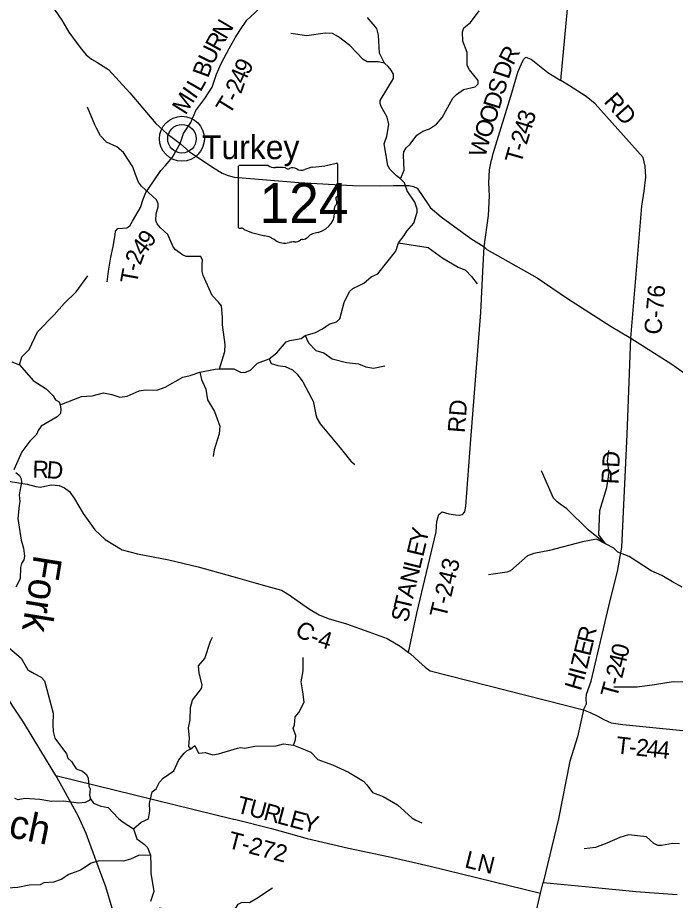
# Model space of a CAD drawing. Extents: x 1525783 to 1900577, y 218250 to 627376.
# Drawn here: x 1696377 to 1707878, y 391777 to 407202 of the extents above; entities that cross this region are included whole.
import ezdxf

# ---------------------------------------------------------------- set-up
doc = ezdxf.new("R2010")
doc.units = 0
for name, color, linetype in [('GM_X_County_Road', 7, 'Continuous'), ('GM_X_County_Road_Text', 7, 'Continuous'), ('GM_X_Minor_River', 7, 'Continuous'), ('GM_X_Minor_River_Text', 7, 'Continuous'), ('GM_X_State_Location', 7, 'Continuous'), ('GM_X_State_Route', 7, 'Continuous'), ('GM_X_State_Shield', 7, 'Continuous'), ('GM_X_Township_Road', 7, 'Continuous'), ('GM_X_Township_Road_Text', 7, 'Continuous'), ('GM_X_Township_ROW', 7, 'Continuous'), ('GM_X_Unincorporated', 7, 'Continuous'), ('GM_X_Unincorporated_Location', 7, 'Continuous'), ('GM_X_Unincorporated_Text', 7, 'Continuous')]:
    doc.layers.add(name, color=color, linetype=linetype)

msp = doc.modelspace()

# ---------------------------------------------------------------- linework, layer by layer
at = {"layer": 'GM_X_County_Road'}
for points in [[(1707101, 401600), (1707294, 403908), (1707330, 404169), (1707360, 404415), (1707349, 404606), (1707314, 404758), (1706872, 405256), (1706475, 405699), (1706320, 405822), (1706009, 406023), (1705874, 406102), (1706079, 408301)], [(1698028, 391638), (1697920, 392012), (1697790, 392354), (1697577, 392945), (1697433, 393255), (1697123, 393824), (1697042, 393959), (1696781, 394389), (1696480, 394888), (1696280, 395190), (1696157, 395389), (1696091, 395495), (1695978, 395695), (1695575, 396785), (1695426, 397233), (1695305, 397657), (1695289, 397853), (1695689, 399162)], [(1695956, 399142), (1696541, 399047), (1696696, 399008), (1696776, 398995), (1696850, 399017), (1696966, 399036), (1697104, 399025), (1697194, 398985), (1697285, 398922), (1697374, 398794), (1697524, 398538), (1697728, 398253), (1697905, 398080), (1698204, 397903), (1698471, 397831), (1699022, 397726), (1699536, 397603), (1700139, 397434), (1700545, 397320), (1700737, 397266), (1700988, 397195), (1701127, 397116), (1701464, 396875), (1701649, 396764), (1701808, 396701), (1702129, 396609), (1702516, 396469), (1702837, 396355), (1703068, 396220), (1703212, 396110), (1703247, 396083), (1703390, 395949), (1703505, 395854), (1703588, 395788), (1706273, 395107), (1706166, 394633), (1706035, 394208), (1705837, 393203), (1705564, 392091), (1706425, 392010), (1707187, 391934), (1707908, 391879)]]:
    msp.add_lwpolyline(points, dxfattribs=at)
at = {"layer": 'GM_X_Minor_River'}
for points in [[(1703073, 404385), (1703133, 404537), (1703124, 404799), (1703132, 404857), (1703171, 404927), (1703243, 404994), (1703355, 405147), (1703465, 405220), (1703580, 405259), (1703704, 405342), (1703803, 405459), (1703986, 405795), (1704049, 405861), (1704172, 405947), (1704380, 405991), (1704430, 406045), (1704431, 406103), (1704277, 406291), (1704236, 406367), (1704238, 406591), (1704162, 406790), (1704158, 406952), (1704178, 407026), (1704295, 407115), (1704447, 407322)], [(1697121, 400436), (1697496, 400583), (1697680, 400593), (1697879, 400645), (1698024, 400618), (1698162, 400572), (1698292, 400589), (1698502, 400679), (1698610, 400696), (1698810, 400694), (1698954, 400743), (1699264, 400922), (1699394, 400947), (1699562, 401007), (1699832, 401060), (1699908, 401066), (1700156, 401063), (1700275, 401006), (1700347, 400999), (1700451, 401040), (1700571, 401165), (1700773, 401241), (1700912, 401346), (1701072, 401537), (1701136, 401562), (1701336, 401598), (1701402, 401647), (1701587, 401702), (1701705, 401762), (1701824, 401845), (1701950, 401886), (1702012, 401942), (1702085, 402223), (1702177, 402416), (1702239, 402472), (1702362, 402529), (1702428, 402560), (1702557, 402673), (1702673, 402728), (1702991, 403123), (1703036, 403267), (1703138, 403394), (1703182, 403473), (1703307, 403610), (1703363, 403802), (1703362, 403858), (1703323, 403976), (1703191, 404176), (1703143, 404318), (1703073, 404385), (1703002, 404438), (1702883, 404553), (1702850, 404617), (1702784, 404996), (1702831, 405132), (1702867, 405338), (1702837, 405466), (1702734, 405647), (1702715, 405700), (1702718, 405754), (1702951, 406138), (1702948, 406216), (1702909, 406286), (1702857, 406347), (1702790, 406409), (1702706, 406580), (1702685, 406895), (1702656, 407011), (1702494, 407207)], [(1702790, 406409), (1702682, 406432), (1702487, 406428), (1702421, 406469), (1702184, 406713), (1701987, 406866), (1701880, 406923), (1701754, 406934), (1701432, 406887), (1701153, 406928)], [(1699908, 401066), (1700001, 401371), (1700004, 401493), (1699962, 401832), (1699961, 401970), (1699939, 402164), (1699892, 402233), (1699781, 402348), (1699623, 402698), (1699602, 402766), (1699603, 402886), (1699612, 402962), (1699578, 403030), (1699323, 403029), (1699257, 403057), (1699136, 403145), (1699095, 403199), (1699005, 403412), (1698876, 403531), (1698817, 403600), (1698791, 403658), (1698801, 403774), (1698836, 403896), (1698836, 403946), (1698807, 404017), (1698540, 404257), (1698490, 404326), (1698440, 404460), (1698391, 404595), (1698230, 404845), (1698111, 404942), (1697928, 405028), (1697823, 405137), (1697757, 405270), (1697727, 405328), (1697597, 405638)], [(1703036, 403267), (1703557, 403185), (1703811, 403001), (1704081, 402842), (1704206, 402787), (1704313, 402680), (1704412, 402549)], [(1696409, 401136), (1696449, 401276), (1696576, 401405), (1696727, 401713), (1697017, 402009), (1697191, 402207), (1697403, 402409), (1697603, 402689)], [(1701402, 401647), (1701461, 401521), (1701591, 401385), (1701729, 401344), (1701874, 401240), (1702127, 401176), (1702336, 401150), (1702468, 401103), (1702599, 401077), (1702799, 401117)], [(1700773, 401241), (1700808, 401161), (1700926, 401126), (1701055, 401108), (1701181, 401047), (1701262, 400972), (1701364, 400841), (1701517, 400553), (1701547, 400501), (1701592, 400267), (1701608, 400206), (1701665, 400106), (1702014, 399682), (1702206, 399450), (1702273, 399395)], [(1696274, 401187), (1696409, 401136), (1696646, 400863), (1696874, 400717), (1696999, 400592), (1697040, 400525), (1697104, 400491), (1697121, 400436), (1697135, 400358), (1697126, 400286), (1697069, 400229), (1696788, 400061), (1696733, 399990), (1696705, 399920), (1696592, 399801), (1696450, 399612), (1696313, 399302)], [(1699562, 401007), (1699593, 400877), (1699665, 400708), (1699697, 400523), (1699819, 400320), (1699910, 400061), (1699901, 399927), (1699812, 399648), (1699795, 399536)], [(1706654, 398009), (1706541, 398164), (1706560, 398590), (1706678, 398992), (1706722, 399251), (1706692, 399454), (1706712, 399638)], [(1696345, 399251), (1696410, 399199), (1696439, 399142), (1696443, 399084), (1696401, 398866), (1696417, 398746), (1696403, 398678), (1696381, 398452), (1696439, 398070), (1696481, 397933), (1696498, 397793), (1696487, 397729), (1696447, 397661), (1696428, 397595), (1696422, 397395), (1696345, 397252)], [(1707995, 397247), (1707826, 397345), (1707639, 397453), (1707454, 397535), (1707069, 397783), (1706872, 397863), (1706803, 397930), (1706654, 398009), (1706353, 398250), (1705981, 398616), (1705862, 398699), (1705810, 398742), (1705745, 398807), (1705540, 399285)], [(1706654, 398009), (1706499, 398091), (1706253, 398043), (1705676, 397889), (1705404, 397837), (1705293, 397798), (1704997, 397533), (1704933, 397510), (1704731, 397482), (1704609, 397467)], [(1699405, 394422), (1699371, 394466), (1699381, 394610), (1699367, 394789), (1699396, 394931), (1699400, 395147), (1699435, 395278), (1699593, 395479), (1699602, 395545), (1699550, 395748), (1699541, 395878), (1699652, 396005), (1699747, 396304), (1699786, 396374)], [(1696169, 396235), (1696436, 396012), (1696554, 395807), (1696665, 395742), (1696787, 395677), (1696846, 395612), (1696996, 395048), (1696992, 394842), (1696999, 394726), (1697028, 394610), (1697231, 394335), (1697256, 394263), (1697317, 394202), (1697398, 394076), (1697511, 394032), (1697583, 393976), (1697610, 393911), (1697623, 393775), (1697648, 393723), (1697633, 393613), (1697650, 393551), (1697704, 393476), (1697831, 393423), (1697957, 393400), (1698138, 393210), (1698202, 393155), (1698400, 393025), (1698459, 392853), (1698587, 392761), (1698649, 392701), (1698703, 392564), (1698704, 392384), (1698708, 392254), (1698761, 391931), (1698701, 391756)], [(1701202, 394491), (1701238, 394584), (1701239, 394660), (1701192, 394781), (1701221, 394845), (1701230, 394983), (1701291, 395058), (1701389, 395243), (1701363, 395420), (1701336, 395596), (1701368, 395786), (1701368, 396022)], [(1709413, 396016), (1709289, 396030), (1709173, 395991), (1708892, 395705), (1708748, 395631), (1708508, 395581), (1707842, 395598), (1707512, 395541), (1707208, 395502), (1706803, 395504)], [(1698400, 393025), (1698535, 393142), (1698668, 393199), (1698691, 393343), (1698682, 393471), (1698732, 393672), (1698801, 393728), (1698856, 393845), (1698923, 393913), (1699110, 394039), (1699193, 394234), (1699288, 394351), (1699341, 394397), (1699405, 394422), (1699476, 394485), (1699540, 394351), (1699606, 394354), (1699658, 394358), (1699788, 394320), (1699892, 394337), (1700224, 394438), (1700274, 394448), (1700348, 394437), (1700522, 394473), (1700896, 394478), (1701024, 394514), (1701202, 394491), (1701434, 394394), (1701502, 394368), (1701625, 394236), (1701881, 394146), (1702162, 394019), (1702424, 393862), (1702483, 393794), (1702580, 393663), (1702771, 393589), (1703019, 393446), (1703268, 393218), (1703342, 393177), (1703447, 393132)], [(1697650, 393551), (1697628, 393521), (1697558, 393486), (1697446, 393473), (1697179, 393509), (1696967, 393502), (1696763, 393538), (1696504, 393556), (1696386, 393531), (1696326, 393556)], [(1707952, 392767), (1707827, 392768), (1707638, 392738), (1707571, 392737), (1707499, 392771), (1707374, 392887), (1707057, 392922), (1706905, 392877), (1706678, 392776), (1706484, 392702), (1706281, 392675)], [(1698703, 392564), (1698492, 392560), (1698351, 392495), (1698229, 392463), (1697803, 392465), (1697661, 392424), (1697474, 392304), (1697270, 392230), (1697137, 392141), (1697005, 392094), (1696837, 392082), (1696769, 392047), (1696581, 392045), (1696379, 392001), (1696193, 391990)], [(1698757, 391509), (1698868, 391646), (1699187, 391545), (1699629, 391442), (1699783, 391393), (1699850, 391384), (1699983, 391437), (1700055, 391496), (1700132, 391614), (1700199, 391649), (1700233, 391713), (1700303, 391748), (1700433, 391741), (1700558, 391815), (1700831, 391995)]]:
    msp.add_lwpolyline(points, dxfattribs=at)
at = {"layer": 'GM_X_State_Route'}
for points in [[(1696852, 407597), (1697148, 407158), (1697274, 406946), (1697380, 406796), (1697491, 406650), (1697576, 406553), (1697667, 406476), (1697762, 406422), (1697875, 406357), (1697963, 406294), (1698338, 405890), (1698794, 405351), (1698988, 405178), (1699218, 405001), (1699384, 404859), (1699813, 404571), (1699956, 404485), (1700058, 404446), (1700165, 404414), (1701295, 404321), (1702235, 404271), (1702717, 404263), (1702941, 404267), (1703221, 404267), (1703301, 404254), (1703364, 404224), (1703560, 403933)], [(1703560, 403933), (1703560, 403932), (1703593, 403884), (1703783, 403723), (1704304, 403344), (1704533, 403197), (1704584, 403152), (1705463, 402654), (1705989, 402295), (1706757, 401806), (1707101, 401600), (1707814, 401148), (1708199, 400875), (1708453, 400713), (1708511, 400666), (1708576, 400627), (1708677, 400482), (1709030, 399904), (1709177, 399656), (1709472, 399355), (1709638, 399191), (1709638, 399191)]]:
    msp.add_lwpolyline(points, dxfattribs=at)
at = {"layer": 'GM_X_State_Shield'}
for p, q in [((1700760, 404616), (1700250, 404616)), ((1701973, 404090), (1701973, 404642)), ((1700233, 404598), (1700233, 403541)), ((1701973, 404090), (1701973, 404090))]:
    msp.add_line(p, q, dxfattribs=at)
for centre, major_axis, start_param, end_param in [((1700253, 404600), (20.2, 0), 1.712693, 3.28349), ((1700881, 404739), (196, 0), 4.042523, 4.731795), ((1701353, 406057), (1845, 0), 4.814394, 5.042369), ((1701954, 404645), (19.4, 0), 6.141152, 7.989035), ((1700946, 404023), (702, 0), 1.404758, 1.657858), ((1701105, 404606), (56.4, 0), 3.836095, 5.185415), ((1701188, 404484), (117, 0), 0.950623, 2.079405), ((1701340, 404651), (141, 0), 4.081561, 5.145723), ((1701589, 404293), (371, 0), 1.699011, 2.107814), ((1701969, 404049), (30, 0), 1.883978, 3.671073), ((1701778, 403979), (180, 0), 5.934695, 6.695948), ((1701953, 404087), (20.7, 0), 5.05454, 6.418171), ((1701457, 403788), (462, 0), 5.101752, 6.440018), ((1702043, 403858), (131, 0), 2.387724, 3.262537), ((1700253, 403539), (20.3, 0), 3.00124, 4.508301), ((1700256, 403647), (155, 0), 4.665946, 4.897461), ((1700288, 403480), (56, 0), 0.519207, 1.627899), ((1700995, 404430), (1333, 0), 4.195997, 4.488961), ((1700597, 403067), (417, 0), 0.823519, 1.323587), ((1701651, 403245), (253, 0), 1.647645, 2.488434), ((1701048, 403475), (265, 0), 4.026481, 4.996735), ((1701201, 403110), (217, 0), 1.495662, 1.94098), ((1701221, 403396), (141, 0), 4.691044, 5.507374), ((1701348, 403294), (39.7, 0), 1.147584, 2.315152), ((1701331, 403439), (149, 0), 4.937069, 5.64225)]:
    msp.add_ellipse(centre, major_axis=major_axis, ratio=0.8, start_param=start_param, end_param=end_param, dxfattribs=at)
at = {"layer": 'GM_X_Township_Road'}
for points in [[(1699218, 405001), (1699277, 405175), (1699408, 405373), (1699495, 405582), (1699649, 405787), (1699776, 405986), (1699853, 406215), (1699934, 406404), (1700076, 406665), (1700181, 406851), (1700260, 406979), (1700385, 407156), (1700523, 407284), (1700654, 407419), (1700753, 407546), (1700807, 407682), (1700878, 407795), (1700951, 407908), (1700990, 408072), (1701055, 409173), (1701041, 409464), (1701066, 409750)], [(1704666, 404722), (1704691, 404830), (1705026, 405908), (1705124, 406248), (1705185, 406394), (1705223, 406473), (1705261, 406511), (1705357, 406478), (1705647, 406245), (1705874, 406102)], [(1697942, 402586), (1697965, 402772), (1698009, 403015), (1698050, 403204), (1698071, 403336), (1698081, 403412), (1698089, 403474), (1698130, 403519), (1698212, 403525), (1698288, 403528), (1698340, 403562), (1698384, 403643), (1698443, 403743), (1698526, 403884), (1698572, 404029), (1698617, 404145), (1698680, 404238), (1698756, 404350), (1698883, 404530), (1698960, 404616), (1699083, 404765), (1699165, 404912), (1699218, 405001)], [(1704302, 399832), (1704302, 399833), (1704474, 402049), (1704514, 402764), (1704533, 403197), (1704608, 403745), (1704628, 404088), (1704614, 404318), (1704625, 404545), (1704665, 404720), (1704666, 404722)], [(1706273, 395107), (1706297, 395151), (1706326, 395210), (1706316, 395298), (1706325, 395378), (1706404, 395609), (1706735, 397014), (1706866, 397526), (1706941, 397949), (1707035, 399916), (1707101, 401600)], [(1703212, 396110), (1703355, 396795), (1703694, 398214), (1703707, 398404), (1703742, 398517), (1703802, 398565), (1703914, 398534), (1704031, 398512), (1704097, 398511), (1704155, 398519), (1704196, 398566), (1704212, 398668), (1704302, 399832)], [(1706273, 395107), (1706389, 395062), (1706520, 394994), (1706628, 394937), (1706753, 394879), (1706961, 394851), (1708067, 394737)], [(1700156, 393196), (1700190, 393188), (1700817, 393034), (1701440, 392860), (1702161, 392688), (1702856, 392542), (1703591, 392375), (1705520, 391904)], [(1705361, 391222), (1705520, 391904), (1705564, 392091)]]:
    msp.add_lwpolyline(points, dxfattribs=at)
at = {"layer": 'GM_X_Township_ROW'}
msp.add_lwpolyline([(1697042, 393959), (1700154, 393197), (1700156, 393196)], dxfattribs=at)
at = {"layer": 'GM_X_Unincorporated'}
for radius in [393, 249]:
    msp.add_circle((1699250, 405086), radius, dxfattribs=at)
at = {"layer": 'GM_X_Unincorporated_Location'}
msp.add_line((1699250, 405086), (1699250, 405086), dxfattribs=at)

# ---------------------------------------------------------------- texts
at = {"layer": 'GM_X_County_Road_Text'}
for s, rotation, p in [('RD', 311.8782, (1706613, 405729)), ('C-76', 85.208, (1707630, 401655)), ('R', 358.4034, (1696633, 399163)), ('D', 355.5147, (1696875, 399157)), ('C', 327.8353, (1701204, 396433)), ('4', 342.8142, (1701606, 396221)), ('-', 338.7751, (1701469, 396274))]:
    msp.add_text(s, height=300, rotation=rotation, dxfattribs=at).set_placement(p)
at = {"layer": 'GM_X_Minor_River_Text'}
for s, rotation, p in [('Fork', 260.8961, (1696663, 397830)), ('Branch', 348.3924, (1694816, 393173))]:
    msp.add_text(s, height=500, rotation=rotation, dxfattribs=at).set_placement(p)
at = {"layer": 'GM_X_State_Location'}
for s in ['s', 'r']:
    msp.add_text(s, height=1, dxfattribs=at).set_placement((1701084, 403999))
msp.add_text('124', height=1, rotation=0, dxfattribs=at).set_placement((1700731, 403927))
at = {"layer": 'GM_X_State_Shield'}
msp.add_text('124', height=696.1, dxfattribs=at).set_placement((1700608, 403616))
at = {"layer": 'GM_X_Township_Road_Text'}
for s, rotation, p in [('N', 59.4698, (1700021, 406805)), ('R', 61.2282, (1699904, 406592)), ('U', 63.5539, (1699788, 406358)), ('R', 62.721, (1705041, 406354)), ('9', 62.3946, (1700413, 406190)), ('B', 70.0012, (1699707, 406135)), ('D', 71.5489, (1704962, 406115)), ('4', 66.6203, (1700342, 406026)), ('L', 60.4706, (1699574, 405891)), ('2', 70.7618, (1700284, 405857)), ('S', 72.9084, (1704876, 405835)), ('M', 57.9714, (1699312, 405489)), ('I', 54.0794, (1699482, 405761)), ('T', 58.2013, (1700080, 405491)), ('-', 63.6953, (1700213, 405709)), ('D', 72.9122, (1704798, 405583)), ('O', 72.9072, (1704721, 405331)), ('3', 72.9623, (1705385, 405321)), ('O', 72.9257, (1704643, 405078)), ('4', 72.9788, (1705331, 405144)), ('2', 73.0166, (1705277, 404967)), ('W', 74.6847, (1704552, 404745)), ('T', 74.0758, (1705180, 404635)), ('-', 73.1624, (1705241, 404849)), ('9', 54.4136, (1698696, 403172)), ('4', 52.6919, (1698578, 403017)), ('2', 69.6047, (1698525, 402864)), ('T', 79.8021, (1698463, 402537)), ('-', 77.5296, (1698502, 402755)), ('RD', 85.5641, (1704195, 399939)), ('RD', 87.0387, (1706882, 399043)), ('Y', 77.8845, (1703522, 397994)), ('E', 76.444, (1703467, 397768)), ('L', 76.4247, (1703414, 397550)), ('T-243', 76.373, (1703868, 396696)), ('N', 76.4205, (1703352, 397293)), ('A', 76.4355, (1703291, 397037)), ('T', 76.8088, (1703239, 396819)), ('S', 77.9865, (1703198, 396622)), ('R', 76.307, (1706441, 396250)), ('E', 76.3053, (1706388, 396032)), ('0', 76.3757, (1707034, 396004)), ('Z', 76.2259, (1706334, 395813)), ('4', 76.3422, (1706990, 395825)), ('I', 75.5223, (1706302, 395690)), ('2', 76.1735, (1706946, 395644)), ('H', 73.3681, (1706223, 395425)), ('-', 75.8628, (1706915, 395523)), ('T', 74.5396, (1706853, 395299)), ('T', 353.4804, (1706828, 394346)), ('2', 354.2559, (1707178, 394308)), ('-', 354.1339, (1707054, 394320)), ('4', 354.2837, (1707362, 394289)), ('4', 354.288, (1707546, 394271)), ('T', 345.0012, (1700187, 393317)), ('U', 344.9954, (1700403, 393259)), ('R', 344.9987, (1700658, 393191)), ('L', 345.0012, (1700896, 393127)), ('E', 345.0844, (1701114, 393069)), ('Y', 346.5726, (1701339, 393009)), ('T-272', 345.4273, (1700034, 392698)), ('LN', 345.9638, (1704178, 392358))]:
    msp.add_text(s, height=300, rotation=rotation, dxfattribs=at).set_placement(p)
at = {"layer": 'GM_X_Unincorporated_Text'}
msp.add_text('Turkey', height=417, rotation=0, dxfattribs=at).set_placement((1699600, 404730))

doc.saveas('drawing.dxf')
